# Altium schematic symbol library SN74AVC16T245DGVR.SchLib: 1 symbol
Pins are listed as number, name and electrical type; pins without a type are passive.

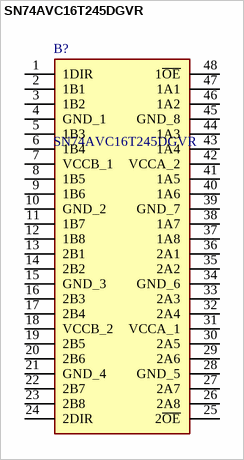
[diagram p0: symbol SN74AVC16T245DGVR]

## SN74AVC16T245DGVR
designator B?
16-Bit Dual-Supply Bus Transceiver with Configurable Voltage-Level Shifting and 3-State Outputs; Manufacturer_Name: Texas Instruments; Geometry.Height: 1.2mm
footprint SOP40P640X120-48N
pins: 1 1DIR, 2 1B1, 3 1B2, 4 GND_1, 5 1B3, 6 1B4, 7 VCCB_1, 8 1B5, 9 1B6, 10 GND_2, 11 1B7, 12 1B8, 13 2B1, 14 2B2, 15 GND_3, 16 2B3, 17 2B4, 18 VCCB_2, 19 2B5, 20 2B6, 21 GND_4, 22 2B7, 23 2B8, 24 2DIR, 25 2~{OE}, 26 2A8, 27 2A7, 28 GND_5, 29 2A6, 30 2A5, 31 VCCA_1, 32 2A4, 33 2A3, 34 GND_6, 35 2A2, 36 2A1, 37 1A8, 38 1A7, 39 GND_7, 40 1A6, 41 1A5, 42 VCCA_2, 43 1A4, 44 1A3, 45 GND_8, 46 1A2, 47 1A1, 48 1~{OE}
